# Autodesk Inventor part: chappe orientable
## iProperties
Created: 2002-05
Part Number: chappe orientable
Material: Par défaut
Document SubType Name: Modélisation
Designer: REVEST Pierre
Control State: 0
Master: False
Checked Out: False
Shininess: 87.0
Length Units: 11269
Angle Units: 11279
Time Units: 11290
Mass Units: 11283
Length Display Precision: 3
Angle Display Precision: 2
Density: 0.0
Volumn: 0.0
Area: 0.0
PropertySet Name: Model Information
Author: REVEST Pierre
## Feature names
1. Extrusion1
2. Extrusion2
3. Congé3 [Fillet]
4. Extrusion3
5. Congé4 [Fillet]
6. Extrusion4
7. Extrusion5
8. Congé5 [Fillet]
9. Congé6 [Fillet]
10. Extrusion7
11. Extrusion8
12. Congé7 [Fillet]
13. Symétrie1 [Mirror]
14. Congé8 [Fillet]
15. Congé9 [Fillet]
16. Congé10 [Fillet]
17. Congé11 [Fillet]
18. Extrusion9
